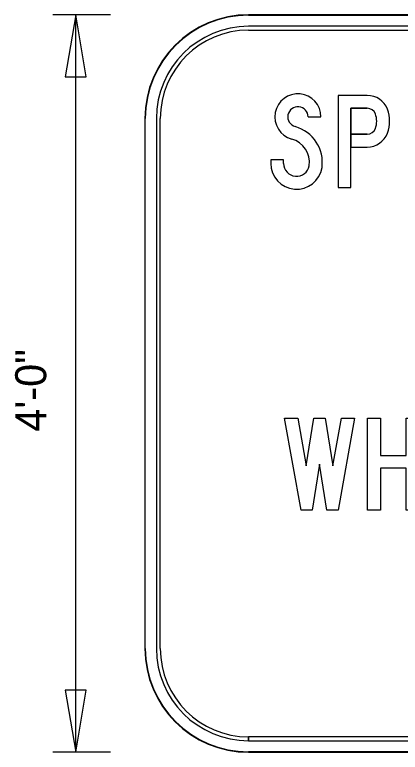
# Model space of a CAD drawing. Extents: x 0 to 770, y 0 to 495.
# Drawn here: x 208.5 to 252, y 221.1 to 304.3 of the extents above; entities that cross this region are included whole.
import ezdxf

# ---------------------------------------------------------------- set-up
doc = ezdxf.new("R2010")
doc.units = 0
for name, color, linetype in [('Dimension', 7, 'Continuous'), ('GSBWFill', 7, 'Continuous'), ('GSColorFill', 7, 'Continuous'), ('GSDims', 7, 'Continuous'), ('GSOutline', 7, 'Continuous'), ('TextStructures', 7, 'Continuous')]:
    doc.layers.add(name, color=color, linetype=linetype)

msp = doc.modelspace()

# ---------------------------------------------------------------- linework, layer by layer
at = {"layer": 'Dimension'}
for points in [[(215.381, 304.265), (214.193, 297.249), (216.57, 297.249)], [(215.381, 221.127), (216.57, 228.143), (214.193, 228.143)]]:
    msp.add_lwpolyline(points, close=True, dxfattribs=at)
at = {"layer": 'GSBWFill'}
for p, q in [((336.192, 304.265), (234.867, 304.265)), ((336.192, 302.966), (234.867, 302.966)), ((234.867, 302.533), (336.192, 302.533)), ((241.57, 292.756), (243.025, 292.756)), ((223.176, 292.574), (223.176, 232.818)), ((224.475, 292.574), (224.475, 232.818)), ((224.908, 232.818), (224.908, 292.574)), ((238.816, 287.508), (238.816, 287.897)), ((234.867, 222.426), (234.867, 222.859)), ((336.192, 222.859), (234.871, 222.859)), ((234.871, 222.859), (234.871, 222.426)), ((234.871, 222.426), (336.192, 222.426)), ((234.867, 221.127), (336.192, 221.127))]:
    msp.add_line(p, q, dxfattribs=at)
for points in [[(248.238, 295.172), (244.948, 295.172), (244.948, 284.78), (246.403, 284.78), (246.403, 293.717), (248.238, 293.717)], [(248.238, 290.807), (246.403, 290.807), (246.403, 289.352), (248.238, 289.352)], [(238.816, 287.897), (237.361, 287.897), (237.361, 287.508)]]:
    msp.add_lwpolyline(points, dxfattribs=at)
for points in [[(241.367, 253.42), (242.227, 258.799), (243.511, 258.799), (244.372, 253.42), (245.34, 258.799), (246.818, 258.799), (244.948, 248.407), (243.701, 248.407), (242.869, 253.603), (242.038, 248.407), (240.791, 248.407), (238.92, 258.799), (240.398, 258.799)], [(248.273, 258.799), (249.728, 258.799), (249.728, 254.59), (252.638, 254.59), (252.638, 258.799), (254.093, 258.799), (254.093, 248.407), (252.638, 248.407), (252.638, 253.135), (249.728, 253.135), (249.728, 248.407), (248.273, 248.407)]]:
    msp.add_lwpolyline(points, close=True, dxfattribs=at)
for centre, radius, start, end in [((234.867, 292.574), 11.691, 90, 180), ((234.867, 292.574), 10.392, 90, 180), ((234.867, 292.574), 9.959, 90, 180), ((240.427, 292.756), 2.598, 0, 254.22594), ((248.238, 292.73), 2.442, 21.1002, 90), ((240.427, 292.756), 1.143, 0, 254.22594), ((248.238, 292.73), 0.987, 21.1002, 90), ((247.026, 292.262), 3.741, 338.8998, 21.10019), ((247.026, 292.262), 2.286, 338.89981, 21.1002), ((238.972, 287.605), 4.209, 352.12977, 74.22594), ((248.238, 291.795), 0.987, 270, 338.8998), ((238.972, 287.605), 2.754, 352.58042, 74.22594), ((248.238, 291.795), 2.442, 270, 338.8998), ((240.271, 287.508), 2.91, 180, 350.53133), ((240.271, 287.508), 1.455, 180, 349.78566), ((234.867, 232.818), 11.691, 180, 270), ((234.867, 232.818), 10.392, 180, 270), ((234.867, 232.818), 9.959, 180, 270)]:
    msp.add_arc(centre, radius, start, end, dxfattribs=at)
at = {"layer": 'GSColorFill'}
for p, q in [((336.192, 304.265), (234.867, 304.265)), ((234.867, 304.222), (336.192, 304.222)), ((336.192, 302.966), (234.867, 302.966)), ((234.867, 302.533), (336.192, 302.533)), ((241.57, 292.756), (243.025, 292.756)), ((223.176, 292.574), (223.176, 232.818)), ((223.219, 232.818), (223.219, 292.574)), ((224.475, 292.574), (224.475, 232.818)), ((224.908, 232.818), (224.908, 292.574)), ((238.816, 287.508), (238.816, 287.897)), ((234.867, 222.426), (234.867, 222.859)), ((336.192, 222.859), (234.871, 222.859)), ((234.871, 222.859), (234.871, 222.426)), ((234.871, 222.426), (336.192, 222.426)), ((234.867, 221.127), (234.867, 221.17)), ((336.192, 221.17), (234.867, 221.17)), ((234.867, 221.17), (234.867, 221.127)), ((234.867, 221.127), (336.192, 221.127))]:
    msp.add_line(p, q, dxfattribs=at)
for points in [[(248.238, 295.172), (244.948, 295.172), (244.948, 284.78), (246.403, 284.78), (246.403, 293.717), (248.238, 293.717)], [(248.238, 290.807), (246.403, 290.807), (246.403, 289.352), (248.238, 289.352)], [(238.816, 287.897), (237.361, 287.897), (237.361, 287.508)]]:
    msp.add_lwpolyline(points, dxfattribs=at)
for points in [[(241.367, 253.42), (242.227, 258.799), (243.511, 258.799), (244.372, 253.42), (245.34, 258.799), (246.818, 258.799), (244.948, 248.407), (243.701, 248.407), (242.869, 253.603), (242.038, 248.407), (240.791, 248.407), (238.92, 258.799), (240.398, 258.799)], [(248.273, 258.799), (249.728, 258.799), (249.728, 254.59), (252.638, 254.59), (252.638, 258.799), (254.093, 258.799), (254.093, 248.407), (252.638, 248.407), (252.638, 253.135), (249.728, 253.135), (249.728, 248.407), (248.273, 248.407)]]:
    msp.add_lwpolyline(points, close=True, dxfattribs=at)
for centre, radius, start, end in [((234.867, 292.574), 11.691, 90, 180), ((234.867, 292.574), 11.648, 90, 180), ((234.867, 292.574), 10.392, 90, 180), ((234.867, 292.574), 9.959, 90, 180), ((240.427, 292.756), 2.598, 0, 254.22594), ((248.238, 292.73), 2.442, 21.1002, 90), ((240.427, 292.756), 1.143, 0, 254.22594), ((248.238, 292.73), 0.987, 21.1002, 90), ((247.026, 292.262), 3.741, 338.8998, 21.10019), ((247.026, 292.262), 2.286, 338.89981, 21.1002), ((238.972, 287.605), 4.209, 352.12977, 74.22594), ((248.238, 291.795), 0.987, 270, 338.8998), ((238.972, 287.605), 2.754, 352.58042, 74.22594), ((248.238, 291.795), 2.442, 270, 338.8998), ((240.271, 287.508), 2.91, 180, 350.53133), ((240.271, 287.508), 1.455, 180, 349.78566), ((234.867, 232.818), 11.691, 180, 270), ((234.867, 232.818), 11.648, 180, 270), ((234.867, 232.818), 10.392, 180, 270), ((234.867, 232.818), 9.959, 180, 270)]:
    msp.add_arc(centre, radius, start, end, dxfattribs=at)
at = {"layer": 'GSDims'}
for p, q in [((219.278, 304.265), (212.783, 304.265)), ((215.381, 221.127), (215.381, 304.265)), ((219.278, 221.127), (212.783, 221.127))]:
    msp.add_line(p, q, dxfattribs=at)
at = {"layer": 'GSOutline'}
for p, q in [((248.238, 295.172), (244.948, 295.172)), ((241.57, 292.756), (243.025, 292.756)), ((238.816, 287.508), (238.816, 287.897))]:
    msp.add_line(p, q, dxfattribs=at)
for points in [[(244.948, 295.172), (244.948, 284.78), (246.403, 284.78), (246.403, 289.352), (248.238, 289.352)], [(248.238, 293.717), (246.403, 293.717), (246.403, 290.807), (248.238, 290.807)], [(238.816, 287.897), (237.361, 287.897), (237.361, 287.508)]]:
    msp.add_lwpolyline(points, dxfattribs=at)
for points in [[(241.367, 253.42), (242.227, 258.799), (243.511, 258.799), (244.372, 253.42), (245.34, 258.799), (246.818, 258.799), (244.948, 248.407), (243.701, 248.407), (242.869, 253.603), (242.038, 248.407), (240.791, 248.407), (238.92, 258.799), (240.398, 258.799)], [(248.273, 258.799), (249.728, 258.799), (249.728, 254.59), (252.638, 254.59), (252.638, 258.799), (254.093, 258.799), (254.093, 248.407), (252.638, 248.407), (252.638, 253.135), (249.728, 253.135), (249.728, 248.407), (248.273, 248.407)]]:
    msp.add_lwpolyline(points, close=True, dxfattribs=at)
for centre, radius, start, end in [((240.427, 292.756), 2.598, 0, 254.22594), ((248.238, 292.73), 2.442, 21.1002, 90), ((240.427, 292.756), 1.143, 0, 254.22594), ((248.238, 292.73), 0.987, 21.1002, 90), ((247.026, 292.262), 3.741, 338.8998, 21.10019), ((247.026, 292.262), 2.286, 338.8998, 21.10019), ((238.972, 287.605), 4.209, 352.12977, 74.22594), ((248.238, 291.795), 0.987, 270, 338.8998), ((238.972, 287.605), 2.754, 352.58042, 74.22594), ((248.238, 291.795), 2.442, 270, 338.8998), ((240.271, 287.508), 2.91, 180, 350.53133), ((240.271, 287.508), 1.455, 180, 349.78566)]:
    msp.add_arc(centre, radius, start, end, dxfattribs=at)

# ---------------------------------------------------------------- texts
at = {"layer": 'TextStructures'}
msp.add_text('4\'-0"', height=3.5, rotation=90, dxfattribs=at).set_placement((212.053, 257.258))

doc.saveas('drawing.dxf')
